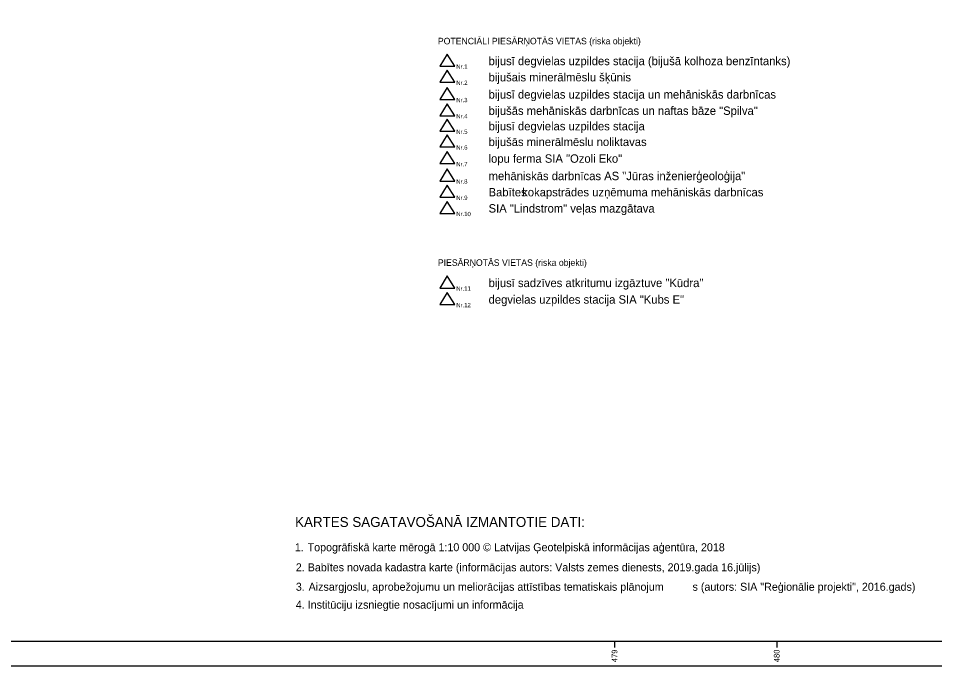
# Model space of a CAD drawing. Extents: x 468834 to 503362, y 294936 to 320859.
# Drawn here: x 475323 to 480974, y 294936 to 298931 of the extents above; entities that cross this region are included whole.
import ezdxf

# ---------------------------------------------------------------- set-up
doc = ezdxf.new("R2010")
doc.units = 0
for name, color, linetype in [('Piesārņota vieta', 7, 'Continuous'), ('Potenciāli piesārņota vieta', 7, 'Continuous'), ('ramis', 7, 'Continuous'), ('Teksts', 7, 'Continuous')]:
    doc.layers.add(name, color=color, linetype=linetype)

msp = doc.modelspace()

# ---------------------------------------------------------------- linework, layer by layer
at = {"layer": 'Piesārņota vieta'}
for p, q in [((477967.7, 297341.6), (477921.4, 297266.9)), ((478013.9, 297266.9), (477967.7, 297341.6)), ((477921.4, 297266.9), (478013.9, 297266.9)), ((477967.7, 297239.4), (477921.4, 297164.7)), ((478013.9, 297164.7), (477967.7, 297239.4)), ((477921.4, 297164.7), (478013.9, 297164.7))]:
    msp.add_line(p, q, dxfattribs=at)
at = {"layer": 'Potenciāli piesārņota vieta'}
for p, q in [((477967.7, 298711.1), (477921.4, 298636.4)), ((478013.9, 298636.4), (477967.7, 298711.1)), ((477921.4, 298636.4), (478013.9, 298636.4)), ((477967.7, 298611.1), (477921.4, 298536.4)), ((478013.9, 298536.4), (477967.7, 298611.1)), ((477921.4, 298536.4), (478013.9, 298536.4)), ((477967.7, 298504.9), (477921.4, 298430.1)), ((478013.9, 298430.1), (477967.7, 298504.9)), ((477921.4, 298430.1), (478013.9, 298430.1)), ((477967.7, 298404.3), (477921.4, 298329.6)), ((478013.9, 298329.6), (477967.7, 298404.3)), ((477921.4, 298329.6), (478013.9, 298329.6)), ((477967.7, 298309), (477921.4, 298234.3)), ((478013.9, 298234.3), (477967.7, 298309)), ((477921.4, 298234.3), (478013.9, 298234.3)), ((477967.7, 298212), (477921.4, 298137.3)), ((478013.9, 298137.3), (477967.7, 298212)), ((477921.4, 298137.3), (478013.9, 298137.3)), ((477967.7, 298109.1), (477921.4, 298034.4)), ((478013.9, 298034.4), (477967.7, 298109.1)), ((477921.4, 298034.4), (478013.9, 298034.4)), ((477967.7, 298001.6), (477921.4, 297926.8)), ((478013.9, 297926.8), (477967.7, 298001.6)), ((477921.4, 297926.8), (478013.9, 297926.8)), ((477967.7, 297901.6), (477921.4, 297826.8)), ((478013.9, 297826.8), (477967.7, 297901.6)), ((477921.4, 297826.8), (478013.9, 297826.8)), ((477967.7, 297801.6), (477921.4, 297726.8)), ((478013.9, 297726.8), (477967.7, 297801.6)), ((477921.4, 297726.8), (478013.9, 297726.8))]:
    msp.add_line(p, q, dxfattribs=at)
at = {"layer": 'ramis'}
for p, q in [((500923.3, 295086.2), (468983.8, 295086.2)), ((479000, 295086.2), (479000, 295048.1)), ((480000, 295086.2), (480000, 295048.1))]:
    msp.add_line(p, q, dxfattribs=at)
msp.add_lwpolyline([(501073.3, 316810.3), (468833.8, 316810.3), (468833.8, 294936.2), (501073.3, 294936.2)], close=True, dxfattribs=at)

# ---------------------------------------------------------------- texts
for s, p in [('479', (479017, 294957.8)), ('480', (480017, 294957.8))]:
    msp.add_text(s, height=35, rotation=90, dxfattribs=at).set_placement(p)
at = {"layer": 'Teksts'}
for s, height, p in [('POTENCIĀLI PIESĀRŅOTĀS VIETAS (riska objekti)', 40, (477910.1, 298771)), ('bijusī degvielas uzpildes stacija (bijušā kolhoza benzīntanks)', 51.84, (478222.8, 298642)), ('Nr.1', 26.54, (478023.5, 298620.2)), ('bijušais minerālmēslu šķūnis', 51.84, (478222.8, 298542.1)), ('Nr.2', 26.54, (478023.5, 298520.2)), ('Nr.3', 26.54, (478023.5, 298413.9)), ('bijusī degvielas uzpildes stacija un mehāniskās darbnīcas', 51.84, (478222.8, 298435.8)), ('bijušās mehāniskās darbnīcas un naftas bāze "Spilva"', 51.84, (478222.8, 298335.2)), ('Nr.4', 26.54, (478023.5, 298313.4)), ('bijusī degvielas uzpildes stacija', 51.84, (478222.8, 298240)), ('Nr.5', 26.54, (478023.5, 298218.1)), ('bijušās minerālmēslu noliktavas', 51.84, (478222.8, 298143)), ('Nr.6', 26.54, (478023.5, 298121.1)), ('Nr.7', 26.54, (478023.5, 298018.2)), ('lopu ferma SIA "Ozoli Eko"', 51.84, (478222.8, 298040)), ('mehāniskās darbnīcas AS "Jūras inženierģeoloģija"', 51.84, (478222.8, 297932.5)), ('Nr.8', 26.54, (478023.5, 297910.6)), ('Babītes', 51.84, (478222.8, 297832.5)), ('kokapstrādes uzņēmuma mehāniskās darbnīcas', 51.84, (478430.1, 297832.5)), ('Nr.9', 26.54, (478023.5, 297810.6)), ('SIA "Lindstrom" veļas mazgātava', 51.84, (478222.8, 297732.5)), ('Nr.10', 26.54, (478023.5, 297710.6)), ('PIESĀRŅOTĀS VIETAS (riska objekti)', 40, (477910.1, 297403.8)), ('bijusī sadzīves atkritumu izgāztuve "Kūdra"', 51.84, (478222.8, 297272.6)), ('Nr.11', 26.54, (478023.5, 297250.7)), ('degvielas uzpildes stacija SIA "Kubs E"', 51.84, (478222.8, 297170.3)), ('Nr.12', 26.54, (478023.5, 297148.5)), ('KARTES SAGATAVOŠANĀ IZMANTOTIE DATI: ', 61.689, (477029.5, 295792.3)), ('1. ', 49.35, (477028, 295642.5)), ('Topogrāfiskā karte mērogā 1:10 000 © Latvijas Ģeotelpiskā informācijas aģentūra, 2018', 49.351, (477106.8, 295642.5)), ('2. Babītes novada kadastra karte (informācijas autors: Valsts zemes dienests, 2019.gada 16.jūlijs)', 49.351, (477034.1, 295518.7)), ('3. ', 49.35, (477034.1, 295398.6)), ('Aizsargjoslu, aprobežojumu un meliorācijas attīstības tematiskais plānojum', 49.351, (477112.8, 295398.6)), ('s (autors: SIA "Reģionālie projekti", 2016.gads)', 49.351, (479480.4, 295398.6)), ('4. Institūciju izsniegtie nosacījumi un informācija', 49.351, (477034.1, 295288.2))]:
    msp.add_text(s, height=height, dxfattribs=at).set_placement(p)

doc.saveas('drawing.dxf')
